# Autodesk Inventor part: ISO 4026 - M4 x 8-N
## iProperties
Created: 2011-01
Part Number: ISO 4026 - M4 x 8-N
Document SubType Name: Modeling
Designer: eric
Density: 1 g/cm^3
Mass: 0.0882623 g
Surface Area: 1.34586 cm^2
Volume: 0.0882623 cm^3
Author: eric
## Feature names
1. Base1
